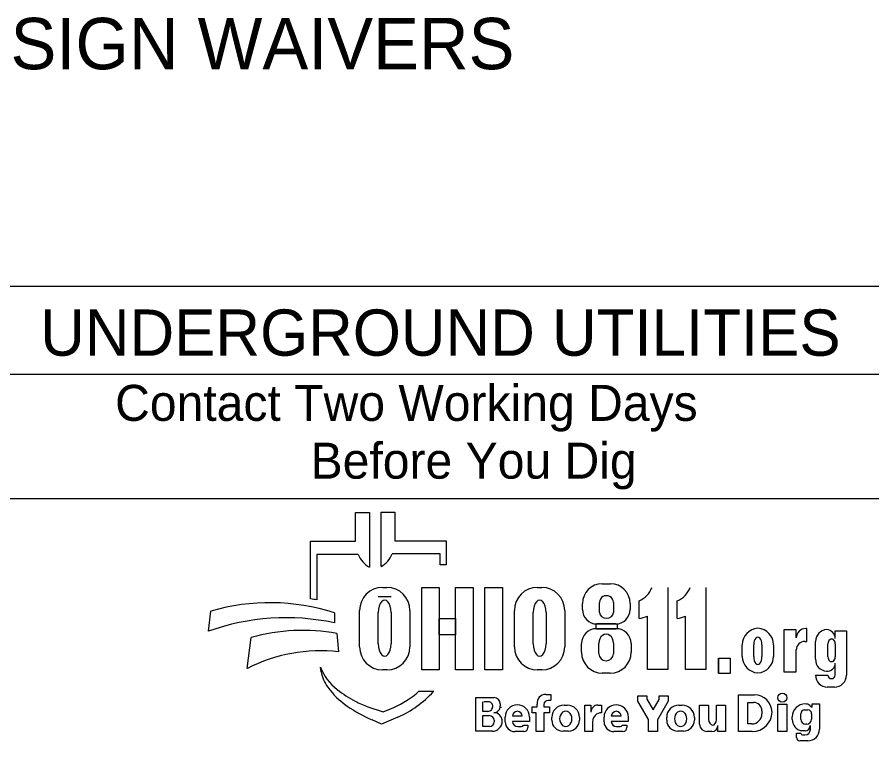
# Model space of a CAD drawing. Extents: x 0 to 34, y -4 to 22.
# Drawn here: x 3.016 to 6.344, y 2.711 to 5.529 of the extents above; entities that cross this region are included whole.
import ezdxf

# ---------------------------------------------------------------- set-up
doc = ezdxf.new("R2010")
doc.units = 0
doc.layers.add('SH_Data', color=7, linetype='Continuous')
doc.layers.add('SH_Text', color=7, linetype='Continuous')

msp = doc.modelspace()

# ---------------------------------------------------------------- linework, layer by layer
at = {"layer": 'SH_Data'}
for p, q in [((7.2275, 4.4803), (2.9775, 4.4803)), ((2.9775, 4.1387), (7.2275, 4.1387)), ((2.9775, 3.6553), (7.2275, 3.6553))]:
    msp.add_line(p, q, dxfattribs=at)
at = {"layer": 'SH_Text'}
for p, q in [((4.3335, 3.4883), (4.3335, 3.5998)), ((4.3335, 3.5998), (4.3872, 3.5998)), ((4.3872, 3.5998), (4.3872, 3.3877)), ((4.4329, 3.39), (4.4329, 3.6021)), ((4.4329, 3.6021), (4.4865, 3.6021)), ((4.4865, 3.6021), (4.4865, 3.4906)), ((4.1576, 3.2644), (4.1576, 3.4883)), ((4.1576, 3.4883), (4.3335, 3.4883)), ((4.4865, 3.4906), (4.6857, 3.4906)), ((4.6857, 3.4906), (4.6857, 3.3968)), ((4.1828, 3.4369), (4.1828, 3.26)), ((4.3439, 3.4369), (4.1828, 3.4369)), ((4.6625, 3.4392), (4.4761, 3.4392)), ((4.6625, 3.3968), (4.6625, 3.4392)), ((4.6857, 3.3968), (4.6625, 3.3968)), ((4.4385, 3.3091), (4.4551, 3.3091)), ((5.0416, 3.3091), (5.0581, 3.3091)), ((5.2931, 3.3231), (5.3258, 3.3231)), ((5.5487, 3.3087), (5.5487, 2.9887)), ((5.6975, 3.3087), (5.6975, 2.9887)), ((4.4718, 3.2721), (4.422, 3.2721)), ((5.2168, 3.2225), (5.2168, 3.2468)), ((5.283, 3.2111), (5.283, 3.2504)), ((5.3371, 3.2504), (5.3371, 3.2111)), ((5.4022, 3.2468), (5.4022, 3.2225)), ((5.4371, 3.188), (5.4371, 3.2562)), ((5.5859, 3.188), (5.5859, 3.2562)), ((3.7602, 3.1381), (3.7696, 3.2162)), ((4.2509, 3.2097), (4.2509, 3.1709)), ((4.3491, 3.0776), (4.3491, 3.2196)), ((4.422, 3.089), (4.422, 3.2114)), ((4.4718, 3.2114), (4.4718, 3.089)), ((4.5445, 3.2196), (4.5445, 3.0776)), ((4.9521, 3.0776), (4.9521, 3.2196)), ((5.025, 3.089), (5.025, 3.2114)), ((5.0748, 3.2114), (5.0748, 3.089)), ((5.1476, 3.2196), (5.1476, 3.0776)), ((5.4694, 2.9887), (5.4694, 3.1973)), ((5.6182, 2.9887), (5.6182, 3.1973)), ((5.3462, 3.1665), (5.2728, 3.1665)), ((4.2608, 3.1291), (4.2671, 3.0582)), ((5.271, 3.1482), (5.3483, 3.1482)), ((6.0493, 3.1436), (6.0005, 3.1436)), ((6.0005, 3.1436), (6.0005, 2.9806)), ((6.0493, 3.112), (6.0493, 3.1436)), ((6.09, 3.1487), (6.086, 3.1487)), ((6.09, 3.0989), (6.09, 3.1487)), ((6.2009, 3.1094), (6.2009, 3.1404)), ((6.2009, 3.1404), (6.2444, 3.1404)), ((6.2444, 3.1404), (6.2444, 2.9675)), ((3.912, 2.9936), (3.9267, 3.1137)), ((6.0823, 3.0989), (6.09, 3.0989)), ((6.1239, 3.029), (6.1239, 3.0986)), ((5.2131, 3.0563), (5.2131, 3.0903)), ((5.2806, 3.0503), (5.2806, 3.0912)), ((5.3374, 3.0912), (5.3374, 3.0503)), ((5.4062, 3.0903), (5.4062, 3.0563)), ((5.8385, 3.0404), (5.8385, 3.0858)), ((5.8835, 3.0396), (5.8835, 3.0858)), ((5.9157, 3.0858), (5.9157, 3.0396)), ((5.9606, 3.0858), (5.9606, 3.0404)), ((6.0493, 2.9806), (6.0493, 3.0659)), ((6.1723, 3.0383), (6.1723, 3.0893)), ((6.2009, 3.0893), (6.2009, 3.0383)), ((5.7456, 3.0337), (5.7456, 2.9737)), ((4.1997, 2.9807), (4.1967, 2.9986)), ((6.2009, 2.9675), (6.2009, 3.0139)), ((4.4551, 2.9882), (4.4385, 2.9882)), ((5.0581, 2.9882), (5.0416, 2.9882)), ((5.3252, 2.9753), (5.2941, 2.9753)), ((5.5487, 2.9887), (5.4694, 2.9887)), ((5.6975, 2.9887), (5.6182, 2.9887)), ((6.0005, 2.9806), (6.0493, 2.9806)), ((6.1239, 2.9675), (6.1723, 2.9675)), ((4.58, 2.9048), (4.6375, 2.9048)), ((6.1977, 2.9208), (6.1707, 2.9208)), ((4.8013, 2.749), (4.8013, 2.8798)), ((4.8013, 2.8798), (4.8725, 2.8798)), ((4.8293, 2.8263), (4.8293, 2.8632)), ((4.8545, 2.8632), (4.8332, 2.8632)), ((5.0739, 2.8926), (5.0934, 2.8926)), ((5.0934, 2.8691), (5.0832, 2.8691)), ((5.0934, 2.8926), (5.0934, 2.8696)), ((5.4319, 2.887), (5.4677, 2.887)), ((5.4319, 2.8655), (5.4319, 2.887)), ((5.4732, 2.7946), (5.4319, 2.8655)), ((5.4677, 2.887), (5.4677, 2.8734)), ((5.4677, 2.8734), (5.4918, 2.832)), ((5.4918, 2.832), (5.5151, 2.8719)), ((5.5509, 2.8655), (5.5088, 2.7932)), ((5.5151, 2.8719), (5.5151, 2.887)), ((5.5151, 2.887), (5.5509, 2.887)), ((5.5509, 2.887), (5.5509, 2.8655)), ((5.8243, 2.8906), (5.8866, 2.8906)), ((5.8243, 2.7478), (5.8243, 2.8906)), ((4.3816, 2.8444), (4.441, 2.8239)), ((4.441, 2.8239), (4.4821, 2.8417)), ((4.8963, 2.856), (4.8963, 2.8481)), ((5.0213, 2.8212), (5.0213, 2.8442)), ((5.0213, 2.8442), (5.0406, 2.8442)), ((5.0406, 2.8442), (5.0406, 2.8546)), ((5.0667, 2.8526), (5.0667, 2.8442)), ((5.0667, 2.8442), (5.0883, 2.8442)), ((5.0883, 2.8442), (5.0883, 2.8212)), ((5.1451, 2.8508), (5.1573, 2.8508)), ((5.2254, 2.7478), (5.2254, 2.8505)), ((5.2254, 2.8505), (5.2499, 2.8505)), ((5.2499, 2.8505), (5.2499, 2.8237)), ((5.2772, 2.8505), (5.291, 2.8505)), ((5.291, 2.8505), (5.291, 2.8209)), ((5.5925, 2.8508), (5.6047, 2.8508)), ((5.6727, 2.8508), (5.7075, 2.8508)), ((5.6727, 2.7762), (5.6727, 2.8508)), ((5.7075, 2.8508), (5.7075, 2.7954)), ((5.7388, 2.7938), (5.7388, 2.8508)), ((5.7388, 2.8508), (5.7736, 2.8508)), ((5.7736, 2.8508), (5.7736, 2.7478)), ((5.8603, 2.7773), (5.8603, 2.8613)), ((5.8603, 2.8613), (5.8828, 2.8613)), ((5.977, 2.8549), (6.0126, 2.8549)), ((5.977, 2.7478), (5.977, 2.8549)), ((6.0126, 2.8549), (6.0126, 2.7478)), ((6.0816, 2.8319), (6.0944, 2.8319)), ((6.1021, 2.8493), (6.1107, 2.8427)), ((6.1107, 2.8553), (6.1395, 2.8553)), ((6.1107, 2.8427), (6.1107, 2.8553)), ((6.1107, 2.8553), (6.1395, 2.8553)), ((6.1395, 2.8553), (6.1395, 2.7567)), ((4.4983, 2.8044), (4.435, 2.7769)), ((4.8487, 2.8263), (4.8293, 2.8263)), ((4.8293, 2.7669), (4.8293, 2.8097)), ((4.8293, 2.8097), (4.8548, 2.8097)), ((4.9159, 2.7858), (4.9159, 2.8042)), ((4.9824, 2.8082), (4.9439, 2.8082)), ((5.0104, 2.8042), (5.0104, 2.7866)), ((5.0362, 2.8212), (5.0213, 2.8212)), ((5.0362, 2.7478), (5.0362, 2.8212)), ((5.0883, 2.8212), (5.0667, 2.8212)), ((5.0667, 2.8212), (5.0667, 2.7478)), ((5.0973, 2.7922), (5.0973, 2.8029)), ((5.2051, 2.8029), (5.2051, 2.7922)), ((5.3008, 2.7858), (5.3008, 2.8042)), ((5.3674, 2.8082), (5.3288, 2.8082)), ((5.3953, 2.8042), (5.3953, 2.7866)), ((5.5447, 2.7922), (5.5447, 2.8029)), ((5.6525, 2.8029), (5.6525, 2.7922)), ((5.9154, 2.8286), (5.9154, 2.8168)), ((6.0335, 2.7953), (6.0335, 2.8054)), ((6.067, 2.7961), (6.067, 2.8173)), ((6.109, 2.8173), (6.109, 2.7961)), ((4.435, 2.7769), (4.3976, 2.7934)), ((4.8546, 2.7669), (4.8293, 2.7669)), ((4.8729, 2.7916), (4.8729, 2.7853)), ((4.9043, 2.7887), (4.9043, 2.7884)), ((5.0104, 2.7866), (4.944, 2.7866)), ((4.9649, 2.7673), (4.979, 2.7673)), ((4.9876, 2.7729), (5.0045, 2.7729)), ((5.0045, 2.7729), (5.0045, 2.7631)), ((5.2559, 2.786), (5.2559, 2.7478)), ((5.3953, 2.7866), (5.3289, 2.7866)), ((5.3498, 2.7673), (5.3639, 2.7673)), ((5.3725, 2.7729), (5.3894, 2.7729)), ((5.3894, 2.7729), (5.3894, 2.7631)), ((5.4732, 2.7478), (5.4732, 2.7946)), ((5.5088, 2.7932), (5.5088, 2.7478)), ((5.7439, 2.7478), (5.7439, 2.7719)), ((5.8759, 2.7773), (5.8603, 2.7773)), ((6.0897, 2.7768), (6.0863, 2.7768)), ((6.1039, 2.7557), (6.1039, 2.7711)), ((4.865, 2.749), (4.8013, 2.749)), ((4.9892, 2.7478), (4.9538, 2.7478)), ((5.0667, 2.7478), (5.0362, 2.7478)), ((5.1623, 2.7494), (5.1401, 2.7494)), ((5.2559, 2.7478), (5.2254, 2.7478)), ((5.3742, 2.7478), (5.3388, 2.7478)), ((5.5088, 2.7478), (5.4732, 2.7478)), ((5.6097, 2.7494), (5.5875, 2.7494)), ((5.7199, 2.7478), (5.7011, 2.7478)), ((5.7736, 2.7478), (5.7439, 2.7478)), ((5.8779, 2.7478), (5.8243, 2.7478)), ((6.0126, 2.7478), (5.977, 2.7478)), ((6.05, 2.7245), (6.05, 2.7415)), ((6.05, 2.7415), (6.067, 2.7415)), ((6.0835, 2.7506), (6.0698, 2.7506)), ((6.0738, 2.7345), (6.0827, 2.7345)), ((6.0942, 2.7114), (6.0631, 2.7114))]:
    msp.add_line(p, q, dxfattribs=at)
for points in [[(4.591, 3.3081), (4.6589, 3.3081), (4.6589, 2.9881), (4.591, 2.9881)], [(4.7231, 3.3081), (4.7911, 3.3081), (4.7911, 2.9881), (4.7231, 2.9881)], [(4.8364, 3.3081), (4.9052, 3.3081), (4.9052, 2.9881), (4.8364, 2.9881)], [(4.6589, 3.1882), (4.7231, 3.1882), (4.7231, 3.1242), (4.6589, 3.1242)], [(5.2706, 3.1665), (5.3523, 3.1665), (5.3523, 3.1481), (5.2706, 3.1481)], [(5.748, 3.0337), (5.7921, 3.0337), (5.7921, 2.9737), (5.748, 2.9737)]]:
    msp.add_lwpolyline(points, close=True, dxfattribs=at)
msp.add_circle((5.9952, 2.8793), 0.0177, dxfattribs=at)
for centre, radius, start, end in [((4.4353, 3.4736), 0.0985, 201.9296, 240.7469), ((4.3847, 3.476), 0.0985, 299.2531, 338.0704), ((4.4385, 3.2196), 0.0895, 90, 180), ((4.4551, 3.2196), 0.0895, 0, 90), ((5.0416, 3.2196), 0.0895, 90, 180), ((5.0581, 3.2196), 0.0895, 0, 90), ((5.2931, 3.2468), 0.0763, 90, 180), ((5.3258, 3.2468), 0.0763, 0, 90), ((5.4031, 3.3379), 0.0885, 292.5572, 340.7355), ((5.552, 3.3379), 0.0885, 292.5572, 340.7355), ((4.0295, 2.4554), 0.8191, 79.2074, 81.0007), ((3.9997, 2.4302), 0.8191, 72.1402, 106.3144), ((5.2728, 3.2225), 0.056, 180, 270), ((5.3462, 3.2225), 0.056, 270, 0), ((5.4291, 3.2761), 0.0885, 275.1733, 297.0931), ((5.5779, 3.2761), 0.0885, 275.1733, 297.0931), ((4.0628, 2.2991), 0.8919, 77.8238, 109.8274), ((4.1267, 2.4094), 0.7322, 79.44, 105.8467), ((5.271, 3.0903), 0.0579, 90, 180), ((5.3483, 3.0903), 0.0579, 0, 90), ((5.9024, 3.0858), 0.064, 92.5886, 180), ((5.8967, 3.0858), 0.064, 0, 87.4114), ((6.086, 3.112), 0.0367, 90, 180), ((6.1698, 3.0986), 0.0459, 92.6865, 180), ((6.1658, 3.1094), 0.0351, 0, 86.9262), ((6.0823, 3.0659), 0.033, 90, 180), ((4.1987, 2.4262), 0.6357, 83.8248, 116.8021), ((4.4385, 3.0776), 0.0895, 180, 270), ((4.4551, 3.0776), 0.0895, 270, 0), ((5.0416, 3.0776), 0.0895, 180, 270), ((5.0581, 3.0776), 0.0895, 270, 0), ((5.2941, 3.0563), 0.081, 180, 270), ((5.3252, 3.0563), 0.081, 270, 0), ((5.9024, 3.0404), 0.064, 180, 267.4114), ((5.8967, 3.0404), 0.064, 272.5886, 0), ((6.1702, 3.029), 0.0463, 180, 265.7132), ((4.3841, 3.0707), 0.2008, 201.0457, 232.5314), ((6.1696, 3.0139), 0.0313, 264.7825, 0), ((4.341, 3.0048), 0.1433, 189.6817, 216.0884), ((6.1707, 2.9675), 0.0468, 180, 270), ((6.1977, 2.9675), 0.0468, 270, 0), ((4.4747, 3.1022), 0.3088, 216.0884, 235.7167), ((4.5766, 3.3219), 0.5173, 232.5314, 241.794), ((4.3387, 3.1722), 0.3602, 293.4582, 312.0712), ((4.3387, 3.1722), 0.401, 293.4582, 317.8286), ((4.4914, 3.1631), 0.3371, 241.794, 250.9821), ((4.8505, 2.8463), 0.0169, 357.8325, 90), ((4.8725, 2.856), 0.0238, 0, 90), ((5.0739, 2.859), 0.0335, 90, 187.5187), ((5.0832, 2.8526), 0.0165, 90, 180), ((5.8866, 2.8223), 0.0682, 0.9944, 90), ((4.6412, 3.3465), 0.6044, 235.7167, 246.2325), ((4.8487, 2.845), 0.0187, 270, 2.0582), ((4.8721, 2.8453), 0.0243, 270, 6.6529), ((4.8827, 2.8438), 0.0175, 347.4023, 0), ((4.9631, 2.8042), 0.0473, 0, 180), ((5.1451, 2.8029), 0.0478, 90, 180), ((5.1573, 2.8029), 0.0478, 0, 90), ((5.2768, 2.8237), 0.0269, 89.2449, 180), ((5.3481, 2.8042), 0.0473, 0, 180), ((5.5925, 2.8029), 0.0478, 90, 180), ((5.6047, 2.8029), 0.0478, 0, 90), ((5.8828, 2.8286), 0.0327, 0, 90), ((6.0834, 2.8054), 0.0499, 89.0934, 180), ((6.0816, 2.8173), 0.0146, 90, 180), ((6.0848, 2.827), 0.0283, 52.1415, 91.2046), ((6.0944, 2.8173), 0.0146, 0, 90), ((4.8548, 2.7916), 0.0181, 0, 90), ((4.8722, 2.7889), 0.0321, 4.0748, 90), ((4.9632, 2.8072), 0.0193, 2.9632, 177.0368), ((5.2908, 2.786), 0.0349, 89.6033, 180), ((5.3481, 2.8072), 0.0193, 2.9632, 177.0368), ((5.8759, 2.8168), 0.0395, 270, 0), ((5.8779, 2.8248), 0.0769, 270, 359.0635), ((6.0863, 2.7961), 0.0193, 180, 270), ((6.0897, 2.7961), 0.0193, 270, 0), ((4.8546, 2.7853), 0.0184, 270, 0), ((4.865, 2.7884), 0.0393, 270, 0), ((4.8714, 2.7887), 0.033, 0, 11.7502), ((4.9538, 2.7858), 0.038, 180, 270), ((4.9649, 2.7883), 0.021, 184.827, 270), ((4.979, 2.7767), 0.00938, 270, 335.9979), ((4.9892, 2.7631), 0.0152, 270, 0), ((5.1401, 2.7922), 0.0428, 180, 270), ((5.1623, 2.7922), 0.0428, 270, 0), ((5.3388, 2.7858), 0.038, 180, 270), ((5.3498, 2.7883), 0.021, 184.827, 270), ((5.3639, 2.7767), 0.00938, 270, 335.9979), ((5.3742, 2.7631), 0.0152, 270, 0), ((5.5875, 2.7922), 0.0428, 180, 270), ((5.6097, 2.7922), 0.0428, 270, 0), ((5.7011, 2.7762), 0.0284, 180, 270), ((5.7199, 2.7719), 0.024, 270, 0), ((6.0791, 2.7953), 0.0457, 180, 258.2203), ((6.0835, 2.771), 0.0203, 270, 0), ((6.0738, 2.7413), 0.00682, 180, 270), ((6.0827, 2.7557), 0.0212, 270, 0), ((6.0942, 2.7567), 0.0453, 270, 0), ((6.0631, 2.7245), 0.0131, 180, 270)]:
    msp.add_arc(centre, radius, start, end, dxfattribs=at)
for centre, major_axis, ratio, start_param, end_param in [((5.31, 3.2504), (0.0271, 0), 0.969373, 0, 3.141593), ((4.4469, 3.2114), (0, 0.0484), 0.514403, 4.712389, 7.853982), ((5.0499, 3.2114), (0, 0.0484), 0.514403, 4.712389, 7.853982), ((5.31, 3.2111), (0.0271, 0), 0.818453, 3.141593, 6.283185), ((5.309, 3.0912), (0, 0.0358), 0.794529, 4.712389, 7.853982), ((5.8996, 3.0858), (0, 0.0291), 0.553236, 4.712389, 7.853982), ((6.1866, 3.0893), (0, 0.0184), 0.777179, 4.712389, 7.853982), ((4.4469, 3.089), (0, 0.0484), 0.514403, 1.570796, 4.712389), ((5.0499, 3.089), (0, 0.0484), 0.514403, 1.570796, 4.712389), ((5.309, 3.0503), (0.0284, 0), 0.959837, 3.141593, 6.283185), ((5.8996, 3.0396), (0, 0.0308), 0.522014, 1.570796, 4.712389), ((6.1866, 3.0383), (0, 0.0184), 0.777179, 1.570796, 4.712389), ((6.1866, 2.9675), (0.0143, 0), 0.959012, 3.141593, 6.283185), ((5.1517, 2.7976), (0, 0.029), 0.832186, 4.712389, 7.853982), ((5.1517, 2.7976), (0, 0.0302), 0.797287, 1.570796, 4.712389), ((5.5991, 2.7976), (0, 0.029), 0.832186, 4.712389, 7.853982), ((5.5991, 2.7976), (0, 0.0302), 0.797287, 1.570796, 4.712389), ((5.7231, 2.7962), (-0.0011, 0.0231), 0.679042, 1.570796, 4.575961)]:
    msp.add_ellipse(centre, major_axis=major_axis, ratio=ratio, start_param=start_param, end_param=end_param, dxfattribs=at)

# ---------------------------------------------------------------- texts
for s, height, p in [('ADA DESIGN WAIVERS', 0.2, (1.9944, 5.3256)), ('UNDERGROUND UTILITIES', 0.18, (3.1057, 4.2106)), ('Contact Two Working Days', 0.14, (3.3972, 3.9571)), ('Before You Dig', 0.14, (4.1583, 3.7321))]:
    msp.add_text(s, height=height, dxfattribs=at).set_placement(p)

doc.saveas('drawing.dxf')
